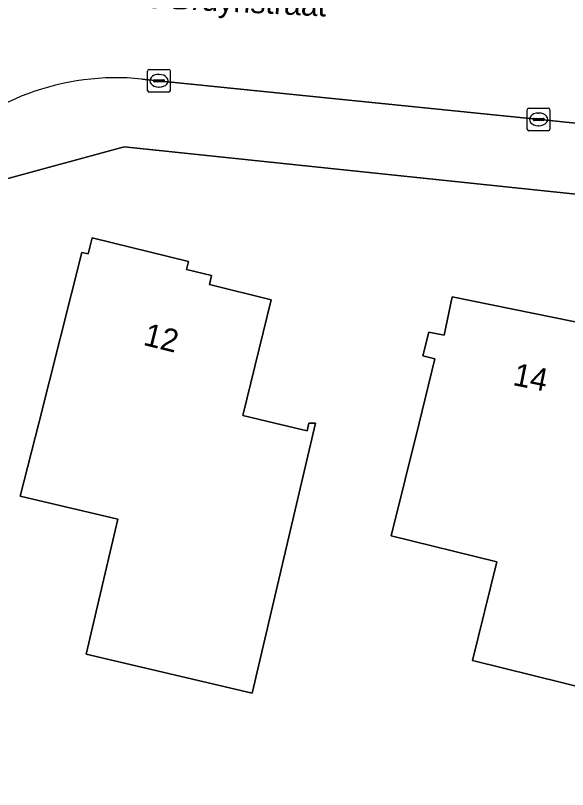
# Model space of a CAD drawing. Extents: x 160030 to 160839, y 385325 to 386450.
# Drawn here: x 160646.44 to 160670.75, y 385483.85 to 385517.96 of the extents above; entities that cross this region are included whole.
import ezdxf

# ---------------------------------------------------------------- set-up
doc = ezdxf.new("R2010")
doc.units = 0
for name, color, linetype in [('IMGEO_Erf', 7, 'Continuous'), ('IMGEO_Kolk', 7, 'Continuous'), ('IMGEO_Openbare_ruimte_label', 7, 'Continuous'), ('IMGEO_Pand', 7, 'Continuous'), ('IMGEO_Pand_nummerreeks', 7, 'Continuous'), ('IMGEO_Rijbaan_lokaal_gesloten', 7, 'Continuous'), ('IMGEO_Rijbaan_lokaal_open', 7, 'Continuous'), ('IMGEO_Voetpad_open', 7, 'Continuous')]:
    doc.layers.add(name, color=color, linetype=linetype)

msp = doc.modelspace()

# ---------------------------------------------------------------- linework, layer by layer
at = {"layer": 'IMGEO_Erf'}
msp.add_lwpolyline([(160708.392, 385506.183), (160651.228, 385512.167), (160645.998, 385510.74), (160635.829, 385500), (160631.087, 385494.991), (160633.869, 385492.281), (160637.63, 385496.281), (160643.473, 385490.788), (160639.711, 385486.787), (160645.856, 385480.839), (160646.216, 385480.49), (160649.004, 385483.407), (160697.517, 385471.795), (160698.361, 385475.23), (160707.118, 385473.113), (160707.343, 385474.036), (160701.941, 385475.351), (160703.959, 385483.642), (160700.623, 385484.455), (160702.03, 385490.236), (160697.658, 385491.3), (160699.773, 385500)], dxfattribs=at)
for points in [[(160656.864, 385488.102), (160649.548, 385489.813), (160650.942, 385495.771), (160646.648, 385496.776), (160647.464, 385500), (160649.366, 385507.517), (160649.642, 385507.449), (160649.82, 385508.168), (160654.054, 385507.123), (160653.967, 385506.769), (160655.075, 385506.495), (160654.977, 385506.098), (160657.703, 385505.425), (160656.448, 385500.338), (160657.856, 385500), (160659.285, 385499.657), (160659.366, 385500), (160659.647, 385500)], [(160674.638, 385487.539), (160666.565, 385489.535), (160667.639, 385493.881), (160662.984, 385495.032), (160664.212, 385500), (160664.911, 385502.828), (160664.387, 385502.957), (160664.647, 385504.008), (160665.322, 385503.871), (160665.665, 385505.562), (160673.692, 385503.934), (160672.729, 385500), (160672.581, 385499.397), (160676.899, 385498.329), (160677.282, 385499.879), (160677.666, 385499.785)]]:
    msp.add_lwpolyline(points, close=True, dxfattribs=at)
at = {"layer": 'IMGEO_Kolk'}
for p, q in [((160652.258, 385514.653), (160652.258, 385515.505)), ((160652.333, 385515.579), (160653.185, 385515.579)), ((160653.259, 385515.505), (160653.259, 385514.653)), ((160652.517, 385515.073), (160652.517, 385515.085)), ((160652.56, 385515.122), (160652.958, 385515.122)), ((160652.746, 385515.359), (160652.771, 385515.359)), ((160653.001, 385515.085), (160653.001, 385515.073)), ((160652.955, 385515.036), (160652.557, 385515.036)), ((160652.769, 385514.799), (160652.744, 385514.799)), ((160653.185, 385514.579), (160652.333, 385514.579)), ((160668.978, 385512.953), (160668.978, 385513.805)), ((160669.053, 385513.879), (160669.905, 385513.879)), ((160669.979, 385513.805), (160669.979, 385512.953)), ((160669.237, 385513.373), (160669.237, 385513.385)), ((160669.28, 385513.422), (160669.678, 385513.422)), ((160669.466, 385513.659), (160669.491, 385513.659)), ((160669.721, 385513.385), (160669.721, 385513.373)), ((160669.675, 385513.336), (160669.277, 385513.336)), ((160669.489, 385513.099), (160669.464, 385513.099)), ((160669.905, 385512.879), (160669.053, 385512.879))]:
    msp.add_line(p, q, dxfattribs=at)
for points in [[(160652.258, 385514.653), (160652.258, 385515.505)], [(160652.333, 385515.579), (160653.185, 385515.579)], [(160653.259, 385515.505), (160653.259, 385514.653)], [(160653.185, 385514.579), (160652.333, 385514.579)], [(160668.978, 385512.953), (160668.978, 385513.805)], [(160669.053, 385513.879), (160669.905, 385513.879)], [(160669.979, 385513.805), (160669.979, 385512.953)], [(160669.905, 385512.879), (160669.053, 385512.879)]]:
    msp.add_lwpolyline(points, dxfattribs=at)
for centre, radius, start, end in [((160652.335, 385515.503), 0.0765, 91.552, 178.448), ((160652.335, 385515.503), 0.0765, 91.552, 178.448), ((160653.183, 385515.503), 0.0765, 1.552, 88.448), ((160653.183, 385515.503), 0.0765, 1.552, 88.448), ((160652.557, 385515.082), 0.0403, 85.8775, 175.7526), ((160652.962, 385515.084), 0.0386, 1.7309, 96.639), ((160652.554, 385515.072), 0.0366, 178.938, 274.7102), ((160652.958, 385515.079), 0.043, 264.8664, 352.4533), ((160652.335, 385514.655), 0.0765, 181.552, 268.448), ((160652.335, 385514.655), 0.0765, 181.552, 268.448), ((160653.183, 385514.655), 0.0765, 271.552, 358.448), ((160653.183, 385514.655), 0.0765, 271.552, 358.448), ((160669.055, 385513.803), 0.0765, 91.552, 178.448), ((160669.055, 385513.803), 0.0765, 91.552, 178.448), ((160669.903, 385513.803), 0.0765, 1.552, 88.448), ((160669.903, 385513.803), 0.0765, 1.552, 88.448), ((160669.277, 385513.382), 0.0403, 85.8775, 175.7526), ((160669.274, 385513.372), 0.0366, 178.938, 274.7102), ((160669.678, 385513.379), 0.043, 264.8664, 352.4533), ((160669.682, 385513.384), 0.0386, 1.7309, 96.639), ((160669.055, 385512.955), 0.0765, 181.552, 268.448), ((160669.055, 385512.955), 0.0765, 181.552, 268.448), ((160669.903, 385512.955), 0.0765, 271.552, 358.448), ((160669.903, 385512.955), 0.0765, 271.552, 358.448)]:
    msp.add_arc(centre, radius, start, end, dxfattribs=at)
for centre, major_axis, ratio, start_param, end_param in [((160652.745, 385515.079), (-0.387, 0.002), 0.722429, 4.712389, 7.853982), ((160652.77, 385515.079), (-0.39, 0.002), 0.717154, 1.570796, 4.712389), ((160669.465, 385513.379), (-0.387, 0.002), 0.722429, 4.712389, 7.853982), ((160669.49, 385513.379), (-0.39, 0.002), 0.717154, 1.570796, 4.712389)]:
    msp.add_ellipse(centre, major_axis=major_axis, ratio=ratio, start_param=start_param, end_param=end_param, dxfattribs=at)
at = {"layer": 'IMGEO_Pand'}
for points in [[(160659.647, 385500), (160659.366, 385500), (160659.285, 385499.657), (160657.856, 385500), (160656.448, 385500.338), (160657.703, 385505.425), (160654.977, 385506.098), (160655.075, 385506.495), (160653.967, 385506.769), (160654.054, 385507.123), (160649.82, 385508.168), (160649.642, 385507.449), (160649.366, 385507.517), (160647.464, 385500), (160646.648, 385496.776), (160650.942, 385495.771), (160649.548, 385489.813), (160656.864, 385488.102)], [(160677.666, 385499.785), (160677.282, 385499.879), (160676.899, 385498.329), (160672.581, 385499.397), (160672.729, 385500), (160673.692, 385503.934), (160665.665, 385505.562), (160665.322, 385503.871), (160664.647, 385504.008), (160664.387, 385502.957), (160664.911, 385502.828), (160664.212, 385500), (160662.984, 385495.032), (160667.639, 385493.881), (160666.565, 385489.535), (160674.638, 385487.539)]]:
    msp.add_lwpolyline(points, close=True, dxfattribs=at)
at = {"layer": 'IMGEO_Rijbaan_lokaal_gesloten'}
msp.add_lwpolyline([(160652.011, 385515.156), (160676.331, 385512.684), (160679.816, 385512.329), (160690.608, 385511.233), (160693.885, 385510.855), (160698.144, 385510.364), (160699.918, 385510.18), (160702.81, 385509.881), (160703.684, 385509.786), (160703.674, 385523.151), (160700.568, 385523.149), (160679.726, 385522.979), (160651.497, 385522.902), (160651.363, 385522.908), (160651.173, 385522.916), (160651.013, 385522.926), (160650.849, 385522.936)], dxfattribs=at)
for centre, radius, start, end in [((160650.235, 385504.932), 18.014, 88.0454, 137.8159), ((160650.885, 385504.055), 11.158, 84.2085, 136.6533)]:
    msp.add_arc(centre, radius, start, end, dxfattribs=at)
at = {"layer": 'IMGEO_Rijbaan_lokaal_open'}
msp.add_arc((160650.235, 385504.932), 18.014, 88.0454, 137.8159, dxfattribs=at)
at = {"layer": 'IMGEO_Voetpad_open'}
for points in [[(160702.81, 385509.881), (160699.918, 385510.18), (160698.144, 385510.364), (160697.902, 385509.889), (160693.828, 385510.359), (160693.885, 385510.855), (160690.608, 385511.233), (160679.816, 385512.329), (160679.764, 385511.832), (160676.279, 385512.187), (160676.331, 385512.684), (160652.011, 385515.156)], [(160597.731, 385459.782), (160627.873, 385491.477), (160632.604, 385486.891), (160641.563, 385478.207), (160642.264, 385477.524), (160642.466, 385477.338), (160645.856, 385480.839), (160639.711, 385486.787), (160633.869, 385492.281), (160631.087, 385494.991), (160635.829, 385500), (160645.998, 385510.74), (160651.228, 385512.167), (160708.392, 385506.183)]]:
    msp.add_lwpolyline(points, dxfattribs=at)
msp.add_arc((160650.885, 385504.055), 11.158, 84.2085, 136.6533, dxfattribs=at)

# ---------------------------------------------------------------- texts
at = {"layer": 'IMGEO_Openbare_ruimte_label'}
msp.add_text('Willem de Bruynstraat', height=1, rotation=357.1919, dxfattribs=at).set_placement((160647.045, 385518.551))
at = {"layer": 'IMGEO_Pand_nummerreeks'}
for s, rotation, p in [('12', 346.132, (160652.028, 385503.449)), ('14', 348.535, (160668.306, 385501.68))]:
    msp.add_text(s, height=1, rotation=rotation, dxfattribs=at).set_placement(p)

doc.saveas('drawing.dxf')
